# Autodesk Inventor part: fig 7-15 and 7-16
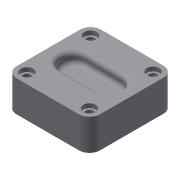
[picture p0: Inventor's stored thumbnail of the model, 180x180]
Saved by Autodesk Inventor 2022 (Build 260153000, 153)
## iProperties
Created: 2001-12
Part Number: fig 7-15 and 7-16
Document SubType Name: Modeling
Designer: Renu Muthoo
Density: 1 g/cm^3
Material: Generic
Appearance: Default
Control State: 0
Master: False
Checked Out: False
Shininess: 77.0
Angle Display Precision: 2
Document Length Units: 11269
Document Angle Units: 11279
Document Time Units: 11290
Document Mass Units: 11283
Document Length Units Precision: 3
Document Angle Units Precision: 2
Density: 0.0
Volumn: 0.0
Area: 0.0
PropertySet Name: Model Information
Author: Renu Muthoo
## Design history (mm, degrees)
sketch "Sketch1"
  geometry: L1 (-20, 20)-(20, 20); L2 (20, 20)-(20, -20.5); L3 (20, -20.5)-(-20, -20.5); L4 (-20, -20.5)-(-20, 20); 1 further point
  constraints: 8 end point, 2 parallel, 1 horizontal, 1 perpendicular, 1 other
  dimensions: "d0" = 40 distance of L1.start L1.end; "d1" = 40.5 distance of L3.end L1.start; "d100" = 20 distance from line of L4 point (0, 0); "d101" = 20 distance from line of L1 point (0, 0)
extrude "Extrusion1" new body sketch "Sketch1" distance "d2" = 15; taper "d3" = 0 deg
workplane "Work Plane1"
workplane "Work Plane2"
workplane "Work Plane3"
workplane "Work Plane4"
fillet "Fillet1" dims "d32" = 5
hole "Hole3" diameter "d66" = 4; stored, may be unused: countersink angle "d70" = 90 deg, drill point angle "d72" = 118 deg; dims "d64" = 10, "d65" = 10, "d67" = 6, "d68" = 6, "d69" = 2, "d71" = 8
hole "Hole4" diameter "d75" = 4; stored, may be unused: countersink angle "d79" = 90 deg, drill point angle "d81" = 118 deg; dims "d73" = 10, "d74" = 10, "d76" = 6, "d77" = 6, "d78" = 2, "d80" = 8
hole "Hole5" diameter "d84" = 4; stored, may be unused: countersink angle "d88" = 90 deg, drill point angle "d90" = 118 deg; dims "d82" = 10, "d83" = 10, "d85" = 6, "d86" = 6, "d87" = 2, "d89" = 8
hole "Hole6" diameter "d93" = 4; stored, may be unused: countersink angle "d97" = 90 deg, drill point angle "d99" = 118 deg; dims "d91" = 10, "d92" = 10, "d94" = 6, "d95" = 6, "d96" = 2, "d98" = 8
fillet "Fillet2" dims "d61" = 2
body "Solid1"
sketch "Sketch8"
  geometry: L1 (-9.844, 1.64)-(1.983, -10.187); L2 (10.469, -1.701)-(-1.358, 10.126); A1 r 6 centre (-5.601, 5.883) between (-1.358, 10.126) and (-9.844, 1.64); A2 r 6 centre (6.226, -5.944) between (1.983, -10.187) and (10.469, -1.701)
  constraints: 4 end point, 4 point on circle, 4 tangent, 2 centre point, 1 parallel
  dimensions: "d29" = 6 radius of A2
extrude "Extrusion2" cut sketch "Sketch8" distance "d30" = 5; taper "d31" = 0 deg
